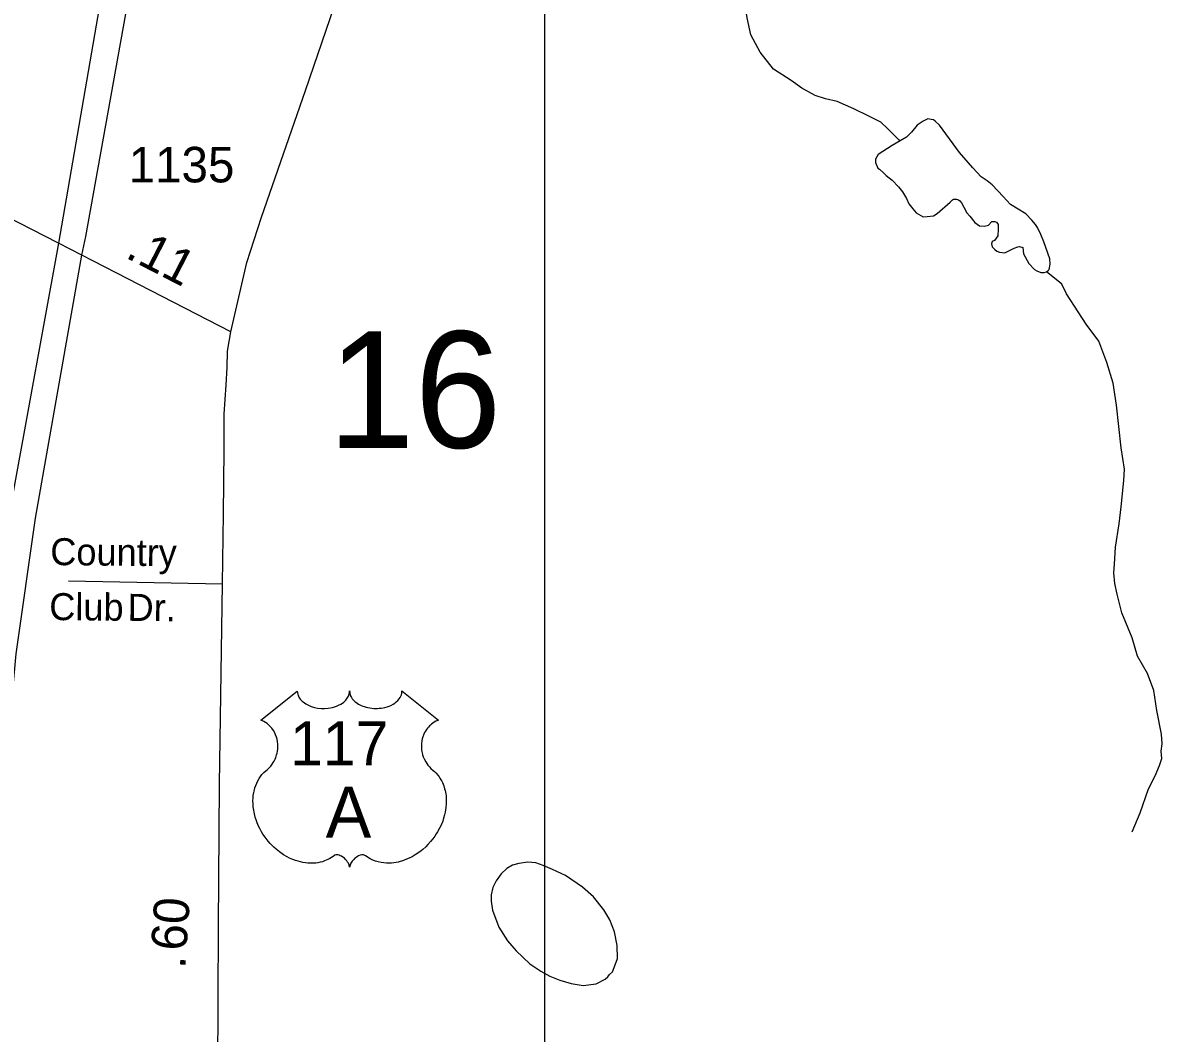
# Model space of a CAD drawing. Extents: x 2206922 to 2357709, y 510027 to 673830.
# Drawn here: x 2280998 to 2285005, y 540388 to 543944 of the extents above; entities that cross this region are included whole.
import ezdxf

# ---------------------------------------------------------------- set-up
doc = ezdxf.new("R2010")
doc.units = 0
for name, color, linetype in [('Exist Hydrographic Misc Water Feature', 7, 'Continuous'), ('Exist Road Non-System Type 51', 7, 'Continuous'), ('Exist Road Non-System Type 51 Label', 7, 'Continuous'), ('Exist Road Primary US Attributed', 7, 'Continuous'), ('Exist Road Primary US Divided Attributed', 7, 'Continuous'), ('Exist Road Primary US Mileage Hundredths English Label', 7, 'Continuous'), ('Exist Road Primary US Shield CELL', 7, 'Continuous'), ('Exist Road Primary US Shield Number Label', 7, 'Continuous'), ('Exist Road Secondary Mileage Hundredths English Label', 7, 'Continuous'), ('Exist Road Secondary Structure Standard Bridge Number Label', 7, 'Continuous'), ('Exist Road Secondary Type 51 Attributed', 7, 'Continuous'), ('Exist Road Secondary Type 51 Number Label', 7, 'Continuous'), ('Map Preparation Inset Cut Line', 7, 'Continuous')]:
    doc.layers.add(name, color=color, linetype=linetype)

msp = doc.modelspace()

# ---------------------------------------------------------------- linework, layer by layer
at = {"layer": 'Exist Hydrographic Misc Water Feature'}
for points in [[(2284083.8, 543528.7), (2284079.9, 543530.9), (2284039.7, 543570.3), (2284015.1, 543594.2), (2283972.8, 543615.6), (2283921, 543641.3), (2283862.3, 543666.7), (2283820.5, 543676.2), (2283784.2, 543687.8), (2283738.3, 543713.3), (2283699.9, 543741), (2283637.6, 543780.4), (2283591, 543840.2), (2283558.4, 543901.8), (2283545.9, 543961.7), (2283533.2, 544039.4), (2283528.3, 544137.1), (2283529.3, 544243.2), (2283554.5, 544305.5)], [(2284597.8, 543067.7), (2284603.6, 543072.1), (2284607.7, 543075.9), (2284611.6, 543094), (2284609.3, 543113.8), (2284588.6, 543173.7), (2284578.6, 543199.5), (2284566.5, 543223.7), (2284559.9, 543233.6), (2284546, 543249.5), (2284525.9, 543271.1), (2284471.9, 543304.4), (2284445.5, 543332.3), (2284406.9, 543373.8), (2284388.9, 543387.9), (2284368.6, 543401.5), (2284338.6, 543433.2), (2284291.9, 543486.9), (2284221.4, 543584.2), (2284207, 543597.7), (2284200.9, 543601.9), (2284192.7, 543603.9), (2284181.2, 543605.7), (2284165, 543597.6), (2284143.4, 543583.4), (2284123.1, 543559.3), (2284105.7, 543541.2), (2284083.8, 543528.7)], [(2284083.8, 543528.7), (2284055.9, 543512.6), (2284006.3, 543479.9), (2283996.4, 543464), (2283996.6, 543451.8), (2284004.6, 543432), (2284010.4, 543428.3), (2284024.7, 543416.4), (2284034.8, 543406.3), (2284054.9, 543390.7), (2284077.2, 543366.7), (2284091.2, 543349.2), (2284105.5, 543325.1), (2284113.5, 543307.3), (2284128.1, 543289.3), (2284140.2, 543275.3), (2284164.1, 543261.6), (2284178.3, 543261.9), (2284200.4, 543264.2), (2284214, 543272.3), (2284259.9, 543312.4), (2284267.5, 543320.6), (2284271.4, 543322.9), (2284281.4, 543322.9), (2284289.2, 543321), (2284293.7, 543317), (2284299.5, 543310.9), (2284307.5, 543295.1), (2284317.7, 543275.3), (2284328.2, 543263.2), (2284346.2, 543241.4), (2284354.4, 543235.3), (2284362.4, 543229.6), (2284380.5, 543227.7), (2284394.2, 543231.7), (2284406.1, 543244.2), (2284416.4, 543244.2), (2284421.9, 543242.2), (2284428.3, 543234.3), (2284428.7, 543218.1), (2284426.6, 543194), (2284415.1, 543177.9), (2284406.7, 543173.9), (2284405.1, 543166.1), (2284406.7, 543156.1), (2284417, 543146), (2284423.3, 543140.2), (2284433.2, 543136.3), (2284451.2, 543134.4), (2284484.9, 543150.8), (2284497.2, 543155), (2284502.9, 543157), (2284515, 543153.1), (2284517.2, 543130.9), (2284535.5, 543097.3), (2284555.8, 543075.6), (2284563.6, 543071.6), (2284577.9, 543065.8), (2284589.8, 543065.6), (2284597.8, 543067.7)], [(2284899.7, 541097.6), (2284927.4, 541164.1), (2284956.7, 541248.5), (2284980.1, 541294.4), (2284995.4, 541330.6), (2285003.2, 541354.6), (2285001.4, 541380.8), (2285005.1, 541406.6), (2285002.8, 541440.6), (2284986, 541524.3), (2284975.1, 541594.4), (2284952.8, 541654.2), (2284918.1, 541715.7), (2284899.7, 541779.3), (2284863, 541867.2), (2284846.2, 541933), (2284838.2, 541970.7), (2284835.5, 542008.8), (2284837.1, 542038.6), (2284840.6, 542098.8), (2284853.9, 542180.8), (2284861.3, 542240.9), (2284870.3, 542332.8), (2284872.2, 542372.7), (2284861.1, 542448.5), (2284843.9, 542598.3), (2284833, 542676.2), (2284810.7, 542748.1), (2284782, 542823.8), (2284737.5, 542883.2), (2284709, 542926.8), (2284668.2, 542990.6), (2284652.2, 543024.6), (2284638, 543036), (2284597.8, 543067.7)], [(2282645.7, 540852.9), (2282649.8, 540821), (2282672.6, 540761.2), (2282702.9, 540713.3), (2282733.1, 540677.9), (2282781.7, 540632.1), (2282819.8, 540606.4), (2282851.8, 540589.1), (2282886.5, 540575.3), (2282926.2, 540563.7), (2282968.3, 540556.1), (2283014.4, 540562.6), (2283046, 540578.9), (2283055.8, 540586.7), (2283061.4, 540594.8), (2283071.6, 540605), (2283077.4, 540619.2), (2283089.1, 540651), (2283088.7, 540696.9), (2283078.4, 540744.7), (2283062, 540786.9), (2283041.5, 540822.4), (2283005.4, 540868), (2282966.8, 540901.8), (2282906.6, 540943.3), (2282860.4, 540964.9), (2282828.6, 540978.6), (2282802.2, 540988.2), (2282774.1, 540990), (2282742.3, 540985.5), (2282720.4, 540979.5), (2282700.5, 540967.5), (2282680.4, 540949), (2282663, 540924.9), (2282651.3, 540900.7), (2282645.1, 540874.9), (2282645.7, 540852.9)]]:
    msp.add_lwpolyline(points, dxfattribs=at)
at = {"layer": 'Exist Road Non-System Type 51'}
msp.add_line((2281158.3, 541979.8), (2281700.1, 541969.9), dxfattribs=at)
at = {"layer": 'Exist Road Primary US Attributed'}
for points in [[(2281730, 542856.2), (2281785.9, 543099.9), (2281837.4, 543259.6), (2281992, 543705.2), (2282224.7, 544385.3), (2282344.2, 544743.1)], [(2281681.8, 539695), (2281683.5, 540225.5), (2281683.7, 540252.9), (2281686.8, 540763.6), (2281690.1, 541265.3), (2281700.1, 541969.9), (2281703.4, 542216), (2281706.8, 542440.4), (2281706.8, 542566.8), (2281713.4, 542669.9), (2281716.7, 542731.4), (2281718.4, 542788), (2281730, 542856.2)]]:
    msp.add_lwpolyline(points, dxfattribs=at)
at = {"layer": 'Exist Road Primary US Divided Attributed'}
for points in [[(2282740.5, 553904.3), (2282594.6, 552678.5), (2282527.3, 552228.9), (2282435.8, 551453.5), (2282363.2, 550882.7), (2282255.6, 550104.6), (2282220.6, 549800.3), (2282191, 549531.1), (2281866.2, 547340.1), (2281713.3, 546468.8), (2281551.5, 545615.2), (2281413.2, 544873.5), (2281266.1, 543996.3), (2281123.2, 543168.4)], [(2281205.4, 543126.5), (2281219.3, 543191.4), (2281360.3, 543975.7), (2281642.7, 545603.5), (2281801.5, 546454.1), (2281951.5, 547287.1), (2282112.9, 548349.1), (2282277.1, 549477.2), (2282312.1, 549803), (2282363.2, 550182.6), (2282524.6, 551431.9), (2282532.7, 551507.3), (2282680.7, 552681.2), (2282835.5, 553895.5)], [(2281123.2, 543168.4), (2280963.1, 542286.2), (2280889.6, 541750.5), (2280839.6, 541200), (2280786.6, 540225.7), (2280721.9, 538730.5), (2280668.9, 537559), (2280645.4, 537093.9), (2280624.8, 536905.5), (2280605.1, 536752.5), (2280579, 536616.1), (2280539, 536445.7), (2280451.7, 536191.7), (2280360.9, 535984.7), (2280213.6, 535718), (2280172.2, 535655.7), (2279502, 534810.1)], [(2279430.3, 534652.5), (2279800, 535100.2), (2280271.8, 535691.3), (2280304.5, 535759.9), (2280414.7, 535956.4), (2280518.9, 536179), (2280609.1, 536421.6), (2280657.2, 536602.1), (2280683.3, 536734.5), (2280710.1, 536879), (2280755.9, 537091), (2280761.4, 537542.5), (2280813.1, 538724.6), (2280851.3, 539451.6), (2280880.8, 540222.8), (2280924.9, 541173.5), (2280974.9, 541724), (2281042.5, 542200.8), (2281205.4, 543126.5)]]:
    msp.add_lwpolyline(points, dxfattribs=at)
at = {"layer": 'Exist Road Primary US Shield CELL'}
msp.add_lwpolyline([(2281963.5, 541592.6), (2281963.8, 541587.2), (2281965.1, 541580.9), (2281966.1, 541577.7), (2281969.1, 541571.4), (2281973.9, 541564.1), (2281980.7, 541556.9), (2281988.4, 541550.5), (2281993.6, 541547.2), (2282002.3, 541542.5), (2282012.3, 541538.3), (2282023.4, 541535.1), (2282034.7, 541532.8), (2282047.1, 541531.5), (2282059.3, 541531.2), (2282072.5, 541532.2), (2282087.1, 541535), (2282093.9, 541536.8), (2282101.4, 541539.4), (2282108.4, 541542.3), (2282116, 541546.4), (2282122.2, 541550.3), (2282127, 541553.8), (2282133.8, 541560.3), (2282139.3, 541567.1), (2282141.5, 541570.9), (2282143.5, 541574.6), (2282146.2, 541582.3), (2282147, 541585.7), (2282147.5, 541592.8), (2282148, 541586.9), (2282148.6, 541583.1), (2282149.6, 541579.5), (2282151.1, 541575.6), (2282153.8, 541570.1), (2282156.9, 541565.6), (2282162.6, 541558.8), (2282166.2, 541555.5), (2282169.4, 541552.8), (2282178.2, 541546.8), (2282188.4, 541541.7), (2282193.4, 541539.4), (2282198.5, 541537.6), (2282205.1, 541535.6), (2282211.8, 541534.1), (2282218.5, 541532.9), (2282225.4, 541531.9), (2282232.3, 541531.4), (2282238, 541531.2), (2282245, 541531.3), (2282251.5, 541531.7), (2282258.1, 541532.5), (2282265.4, 541533.7), (2282271.2, 541535), (2282279, 541537), (2282286, 541539.5), (2282292.1, 541542.2), (2282300.1, 541546.4), (2282306.5, 541550.4), (2282311.3, 541554.2), (2282316.9, 541559.4), (2282322.2, 541565.5), (2282325.3, 541570), (2282327.5, 541574.6), (2282329.6, 541579.5), (2282330.8, 541584.7), (2282331.4, 541589.1), (2282331.5, 541593), (2282460.1, 541490.5), (2282457.1, 541489.4), (2282450.1, 541486), (2282444.6, 541482.7), (2282435.7, 541476.5), (2282431.9, 541473), (2282428.1, 541469.5), (2282424.6, 541465.7), (2282421.6, 541462.1), (2282417.8, 541456.9), (2282414.5, 541451.8), (2282411.2, 541446.1), (2282408.8, 541441.1), (2282404.9, 541430.8), (2282403, 541424.3), (2282401.8, 541418.7), (2282400.3, 541407.2), (2282399.9, 541401.8), (2282399.9, 541396.4), (2282400.2, 541390.7), (2282400.7, 541385.2), (2282401.7, 541379.5), (2282402.6, 541374.5), (2282404.2, 541368.3), (2282406.5, 541361.2), (2282409.3, 541354.3), (2282415.2, 541343.1), (2282422.7, 541331.7), (2282428.1, 541325.3), (2282433.4, 541319.8), (2282441.4, 541313.2), (2282445.7, 541309.4), (2282450.6, 541304.4), (2282458.7, 541295.1), (2282461.9, 541290.7), (2282465.2, 541285.7), (2282468.3, 541280.6), (2282471.3, 541275.2), (2282473.7, 541270.4), (2282478.3, 541259.4), (2282481.6, 541248.6), (2282483.1, 541243), (2282485.5, 541230.4), (2282486.4, 541224.2), (2282487.4, 541211.9), (2282487.4, 541197), (2282486.3, 541182.8), (2282483.6, 541166.4), (2282481.4, 541156.5), (2282478, 541145), (2282474.8, 541135), (2282468.9, 541120.4), (2282463.7, 541109.7), (2282456.9, 541097.3), (2282452.3, 541089.8), (2282446.9, 541081.7), (2282440.1, 541072.4), (2282432.2, 541062.6), (2282422.7, 541052.1), (2282415.1, 541044.5), (2282405, 541035.5), (2282399, 541030.5), (2282390.3, 541024), (2282378.5, 541016), (2282366.8, 541009.3), (2282356.8, 541004.2), (2282348, 541000.4), (2282336.6, 540996.1), (2282317.6, 540990.8), (2282310.7, 540989.4), (2282302.5, 540988.2), (2282294.9, 540987.4), (2282287.4, 540986.9), (2282277.4, 540986.9), (2282267.4, 540987.7), (2282258, 540989.1), (2282248.2, 540991.1), (2282238, 540994.2), (2282228.7, 540997.8), (2282219.2, 541002.4), (2282203.3, 541012.5), (2282198.7, 541014.9), (2282196.2, 541015.6), (2282190, 541015.9), (2282184.2, 541014.7), (2282178.3, 541012.3), (2282174.7, 541010.4), (2282170, 541007.3), (2282166.3, 541004.4), (2282161.9, 541000.2), (2282158.9, 540996.7), (2282156.6, 540994), (2282152.1, 540986.9), (2282150.5, 540983.6), (2282148.8, 540979.3), (2282147.4, 540972.9), (2282145.3, 540980.9), (2282143, 540986.3), (2282140.3, 540990.8), (2282137.4, 540994.8), (2282132.9, 541000), (2282128.9, 541003.9), (2282124, 541007.8), (2282118.9, 541011), (2282114.7, 541013.1), (2282110.9, 541014.5), (2282106.3, 541015.7), (2282102.5, 541016), (2282099.4, 541015.9), (2282095.1, 541014.9), (2282089.3, 541010.7), (2282083.8, 541006.9), (2282077.8, 541003.2), (2282070.7, 540999.4), (2282065.4, 540997), (2282059.2, 540994.5), (2282051.9, 540992.1), (2282044, 540990.1), (2282035.9, 540988.5), (2282028.7, 540987.3), (2282021.1, 540986.6), (2282014.1, 540986.4), (2282006.9, 540986.5), (2282000.2, 540987), (2281992.4, 540987.7), (2281982.6, 540989.1), (2281974.6, 540991), (2281966.1, 540993.3), (2281957.3, 540996), (2281948, 540999.6), (2281936.3, 541004.7), (2281928.2, 541008.8), (2281915.3, 541016.2), (2281900.3, 541026.6), (2281888.9, 541035.8), (2281880.6, 541043.3), (2281868.4, 541055.8), (2281861.2, 541063.9), (2281850, 541078.5), (2281842.7, 541089.1), (2281838.1, 541096.8), (2281831.2, 541109.3), (2281827.5, 541117.1), (2281822.6, 541128.5), (2281818.8, 541138.9), (2281815.6, 541148.8), (2281813.9, 541155.1), (2281811.4, 541166.1), (2281810, 541173.9), (2281808.5, 541184.7), (2281807.7, 541196), (2281807.6, 541206.4), (2281807.8, 541215.1), (2281808.8, 541225.2), (2281810.5, 541235.9), (2281812.6, 541245.1), (2281814.4, 541251.7), (2281817.2, 541259.7), (2281820.8, 541268.6), (2281825, 541277.1), (2281829.1, 541284.2), (2281834.2, 541291.8), (2281839.2, 541298.3), (2281845.8, 541305.4), (2281852.6, 541311.9), (2281858.9, 541317), (2281866.3, 541324.3), (2281870.2, 541328.7), (2281874.9, 541334.9), (2281878.6, 541340.6), (2281881.6, 541345.7), (2281885.5, 541353.2), (2281887.8, 541358.8), (2281890.8, 541367.5), (2281892.3, 541373.6), (2281893.8, 541381.4), (2281894.8, 541388.8), (2281895.1, 541398), (2281894.9, 541405.6), (2281893.9, 541414.4), (2281892.3, 541423), (2281890.2, 541430.4), (2281887.1, 541438.9), (2281884.1, 541445.1), (2281879.2, 541453.6), (2281873.7, 541461.4), (2281868.1, 541467.8), (2281862.4, 541473.5), (2281856.9, 541477.7), (2281851.7, 541481.5), (2281845.2, 541485.4), (2281838.9, 541488.5), (2281834.9, 541490.1)], close=True, dxfattribs=at)
at = {"layer": 'Exist Road Secondary Type 51 Attributed'}
for points in [[(2281123.2, 543168.4), (2280845.4, 543310.3), (2280608.2, 543438), (2280491.8, 543494.9)], [(2281205.4, 543126.5), (2281123.2, 543168.4)], [(2281730, 542856.2), (2281247.2, 543104.8), (2281205.4, 543126.5)]]:
    msp.add_lwpolyline(points, dxfattribs=at)
at = {"layer": 'Map Preparation Inset Cut Line'}
msp.add_lwpolyline([(2282834.5, 540252.9), (2282834.5, 546746.4), (2271763.2, 546746.4), (2271763.2, 540252.9)], dxfattribs=at)

# ---------------------------------------------------------------- texts
at = {"layer": 'Exist Road Non-System Type 51 Label'}
for s, p in [('Country', (2281094.4, 542035.8)), ('Club', (2281090.8, 541842.4)), ('Dr.', (2281366.2, 541839.7))]:
    msp.add_text(s, height=95, rotation=359.4335, dxfattribs=at).set_placement(p)
at = {"layer": 'Exist Road Primary US Mileage Hundredths English Label'}
for s, p in [('60', (2281573.4, 540676.4)), ('.', (2281569.2, 540614))]:
    msp.add_text(s, height=125, rotation=86.1187, dxfattribs=at).set_placement(p)
at = {"layer": 'Exist Road Primary US Shield Number Label'}
for s, height, p in [('117', 155, (2281937.9, 541331.2)), ('A', 180, (2282063.1, 541076.4))]:
    msp.add_text(s, height=height, dxfattribs=at).set_placement(p)
at = {"layer": 'Exist Road Secondary Mileage Hundredths English Label'}
msp.add_text('.11', height=125, rotation=332.754, dxfattribs=at).set_placement((2281354.9, 543119.6))
at = {"layer": 'Exist Road Secondary Structure Standard Bridge Number Label'}
msp.add_text('16', height=410.1, dxfattribs=at).set_placement((2282071.1, 542448.2))
at = {"layer": 'Exist Road Secondary Type 51 Number Label'}
msp.add_text('1135', height=125, dxfattribs=at).set_placement((2281370.3, 543382.3))

doc.saveas('drawing.dxf')
